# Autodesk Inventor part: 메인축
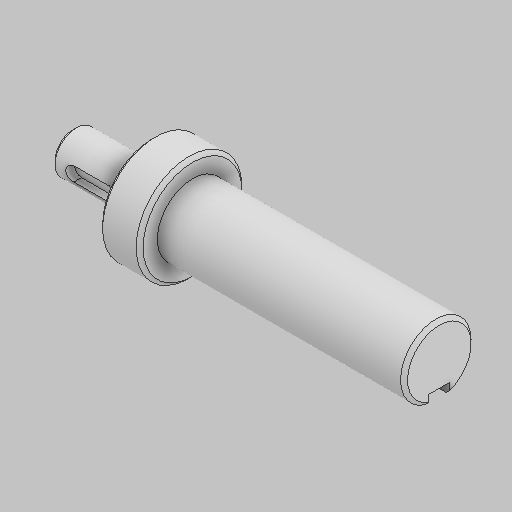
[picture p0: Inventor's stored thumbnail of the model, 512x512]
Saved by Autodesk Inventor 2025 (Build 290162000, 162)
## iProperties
Created: 2024-08
Part Number: 메인축
Material: 강철, 연강
Document SubType Name: Modeling
Designer: 현기
Density: 7.85 g/cm^3
Appearance: 반연마
Mass: 251.633 g
Surface Area: 77.4404 cm^2
Volume: 32.0551 cm^3
Sending System: Autodesk Inventor 2025
Preprocessor: ST-DEVELOPER v20
Author: jhkim
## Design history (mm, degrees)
feature "솔리드1"
node "작업 평면1"
  node "작업축1"
node "솔리드2"
other parameters: "d0" = 15.70796
